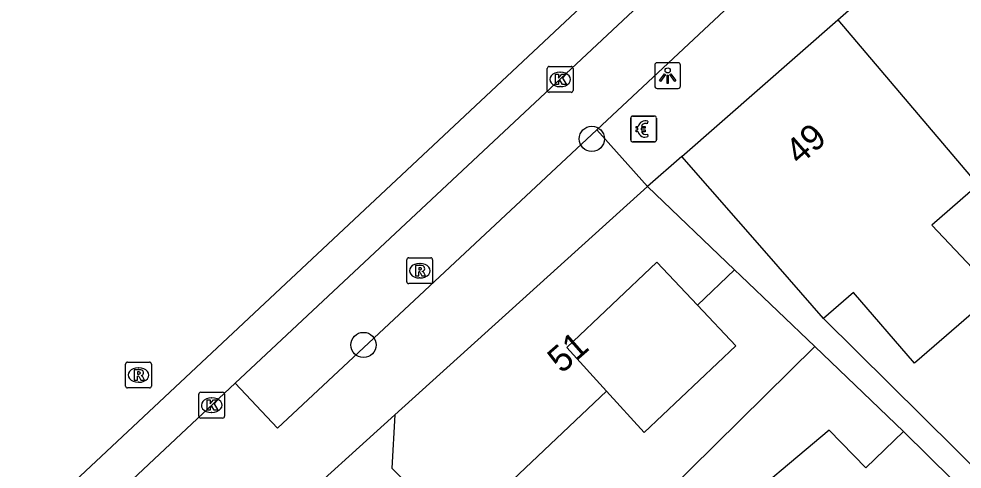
# Model space of a CAD drawing. Extents: x 160107 to 160928, y 382056 to 382918.
# Drawn here: x 160691.3 to 160727.88, y 382812.64 to 382830.08 of the extents above; entities that cross this region are included whole.
import ezdxf

# ---------------------------------------------------------------- set-up
doc = ezdxf.new("R2010")
doc.units = 0
for name, color, linetype in [('IMGEO_Betaalautomaat', 7, 'Continuous'), ('IMGEO_Boom', 7, 'Continuous'), ('IMGEO_Kolk', 7, 'Continuous'), ('IMGEO_Lichtpunt', 7, 'Continuous'), ('IMGEO_Pand', 7, 'Continuous'), ('IMGEO_Pand_nummerreeks', 7, 'Continuous'), ('IMGEO_Rijbaan_lokaal_gesloten', 7, 'Continuous'), ('IMGEO_Rioolput', 7, 'Continuous'), ('IMGEO_Voetpad_open', 7, 'Continuous')]:
    doc.layers.add(name, color=color, linetype=linetype)

msp = doc.modelspace()

# ---------------------------------------------------------------- linework, layer by layer
at = {"layer": 'IMGEO_Betaalautomaat'}
for p, q in [((160715.101, 382826.311), (160715.942, 382826.311)), ((160715.942, 382826.311), (160715.101, 382826.311)), ((160715.026, 382825.387), (160715.026, 382826.228)), ((160715.026, 382826.228), (160715.026, 382825.387)), ((160715.688, 382826.116), (160715.671, 382826.016)), ((160716.025, 382826.237), (160716.025, 382825.396)), ((160716.025, 382825.396), (160716.025, 382826.237)), ((160715.309, 382825.775), (160715.309, 382825.843)), ((160715.43, 382825.843), (160715.43, 382825.775)), ((160715.675, 382825.61), (160715.697, 382825.523)), ((160715.951, 382825.312), (160715.11, 382825.312)), ((160715.11, 382825.312), (160715.951, 382825.312))]:
    msp.add_line(p, q, dxfattribs=at)
for points in [[(160715.309, 382825.843), (160715.24, 382825.843), (160715.24, 382825.912), (160715.319, 382825.912)], [(160715.314, 382825.706), (160715.24, 382825.706), (160715.24, 382825.775), (160715.309, 382825.775)], [(160715.441, 382825.912), (160715.588, 382825.912), (160715.588, 382825.843), (160715.43, 382825.843)], [(160715.43, 382825.775), (160715.588, 382825.775), (160715.588, 382825.706), (160715.444, 382825.706)]]:
    msp.add_lwpolyline(points, dxfattribs=at)
for centre, radius, start, end in [((160715.104, 382826.234), 0.0779, 92.4484, 184.2845), ((160715.104, 382826.234), 0.0779, 92.4484, 184.2845), ((160715.948, 382826.234), 0.0779, 2.4484, 94.2845), ((160715.948, 382826.234), 0.0779, 2.4484, 94.2845), ((160715.602, 382825.836), 0.293, 73.014, 165.0139), ((160715.608, 382825.849), 0.179, 69.3236, 159.5683), ((160715.575, 382825.761), 0.267, 191.8096, 297.0389), ((160715.608, 382825.776), 0.179, 202.7625, 291.8693), ((160715.104, 382825.39), 0.0779, 182.4484, 274.2845), ((160715.104, 382825.39), 0.0779, 182.4484, 274.2845), ((160715.948, 382825.39), 0.0779, 272.4484, 4.2845), ((160715.948, 382825.39), 0.0779, 272.4484, 4.2845)]:
    msp.add_arc(centre, radius, start, end, dxfattribs=at)
at = {"layer": 'IMGEO_Boom'}
for centre in [(160713.52, 382825.428), (160704.663, 382817.445)]:
    msp.add_circle(centre, 0.489, dxfattribs=at)
at = {"layer": 'IMGEO_Kolk'}
for p, q in [((160711.788, 382827.306), (160711.788, 382828.158)), ((160711.863, 382828.232), (160712.715, 382828.232)), ((160712.789, 382828.158), (160712.789, 382827.306)), ((160712.276, 382828.012), (160712.301, 382828.012)), ((160712.299, 382827.452), (160712.274, 382827.452)), ((160712.715, 382827.232), (160711.863, 382827.232)), ((160698.276, 382814.687), (160698.276, 382815.539)), ((160698.351, 382815.613), (160699.203, 382815.613)), ((160698.764, 382815.393), (160698.789, 382815.393)), ((160699.277, 382815.539), (160699.277, 382814.687)), ((160699.203, 382814.613), (160698.351, 382814.613)), ((160698.787, 382814.833), (160698.762, 382814.833))]:
    msp.add_line(p, q, dxfattribs=at)
for points in [[(160711.788, 382827.306), (160711.788, 382828.158)], [(160711.863, 382828.232), (160712.715, 382828.232)], [(160712.789, 382828.158), (160712.789, 382827.306)], [(160712.109, 382827.932), (160712.232, 382827.932), (160712.232, 382827.781), (160712.362, 382827.932), (160712.526, 382827.932), (160712.38, 382827.781), (160712.533, 382827.532), (160712.381, 382827.532), (160712.296, 382827.696), (160712.232, 382827.629), (160712.232, 382827.532), (160712.109, 382827.532), (160712.109, 382827.932)], [(160712.715, 382827.232), (160711.863, 382827.232)], [(160698.276, 382814.687), (160698.276, 382815.539)], [(160698.351, 382815.613), (160699.203, 382815.613)], [(160699.277, 382815.539), (160699.277, 382814.687)], [(160698.597, 382815.313), (160698.72, 382815.313), (160698.72, 382815.162), (160698.85, 382815.313), (160699.014, 382815.313), (160698.868, 382815.162), (160699.021, 382814.913), (160698.869, 382814.913), (160698.784, 382815.077), (160698.72, 382815.01), (160698.72, 382814.913), (160698.597, 382814.913), (160698.597, 382815.313)], [(160699.203, 382814.613), (160698.351, 382814.613)]]:
    msp.add_lwpolyline(points, dxfattribs=at)
for centre, start, end in [((160711.865, 382828.156), 91.552, 178.448), ((160711.865, 382828.156), 91.552, 178.448), ((160712.713, 382828.156), 1.552, 88.448), ((160712.713, 382828.156), 1.552, 88.448), ((160711.865, 382827.308), 181.552, 268.448), ((160711.865, 382827.308), 181.552, 268.448), ((160712.713, 382827.308), 271.552, 358.448), ((160712.713, 382827.308), 271.552, 358.448), ((160698.353, 382815.537), 91.552, 178.448), ((160698.353, 382815.537), 91.552, 178.448), ((160699.201, 382815.537), 1.552, 88.448), ((160699.201, 382815.537), 1.552, 88.448), ((160698.353, 382814.689), 181.552, 268.448), ((160698.353, 382814.689), 181.552, 268.448), ((160699.201, 382814.689), 271.552, 358.448), ((160699.201, 382814.689), 271.552, 358.448)]:
    msp.add_arc(centre, 0.0765, start, end, dxfattribs=at)
for centre, major_axis, ratio, start_param, end_param in [((160712.275, 382827.732), (-0.387, 0.002), 0.722429, 4.712389, 7.853982), ((160712.3, 382827.732), (-0.39, 0.002), 0.717154, 1.570796, 4.712389), ((160698.763, 382815.113), (-0.387, 0.002), 0.722429, 4.712389, 7.853982), ((160698.788, 382815.113), (-0.39, 0.002), 0.717154, 1.570796, 4.712389)]:
    msp.add_ellipse(centre, major_axis=major_axis, ratio=ratio, start_param=start_param, end_param=end_param, dxfattribs=at)
at = {"layer": 'IMGEO_Lichtpunt'}
for p, q in [((160715.961, 382828.283), (160715.961, 382827.476)), ((160715.961, 382828.283), (160715.961, 382827.476)), ((160716.863, 382828.378), (160716.055, 382828.378)), ((160716.863, 382828.378), (160716.055, 382828.378)), ((160716.957, 382827.476), (160716.957, 382828.283)), ((160716.957, 382827.476), (160716.957, 382828.283)), ((160716.055, 382827.382), (160716.863, 382827.382)), ((160716.055, 382827.382), (160716.863, 382827.382))]:
    msp.add_line(p, q, dxfattribs=at)
for points in [[(160716.335, 382827.947), (160716.374, 382827.919), (160716.186, 382827.657), (160716.148, 382827.684), (160716.335, 382827.947)], [(160716.437, 382827.899), (160716.484, 382827.899), (160716.484, 382827.577), (160716.437, 382827.577), (160716.437, 382827.899)], [(160716.547, 382827.919), (160716.585, 382827.946), (160716.772, 382827.684), (160716.733, 382827.656), (160716.547, 382827.919)]]:
    msp.add_lwpolyline(points, dxfattribs=at)
msp.add_circle((160716.46, 382828.081), 0.0994, dxfattribs=at)
for centre, start, end in [((160716.055, 382828.283), 90, 180), ((160716.055, 382828.283), 90, 180), ((160716.863, 382828.283), 0, 90), ((160716.863, 382828.283), 0, 90), ((160716.055, 382827.476), 180, 270), ((160716.055, 382827.476), 180, 270), ((160716.863, 382827.476), 270, 0), ((160716.863, 382827.476), 270, 360)]:
    msp.add_arc(centre, 0.0946, start, end, dxfattribs=at)
at = {"layer": 'IMGEO_Pand'}
for points in [[(160723.059, 382830.039), (160730.515, 382836.564), (160731.934, 382836.459), (160732.286, 382836.117)], [(160717.009, 382824.744), (160723.059, 382830.039)], [(160723.059, 382830.039), (160728.206, 382823.984)], [(160722.503, 382818.469), (160720.302, 382820.982), (160717.009, 382824.744)], [(160728.206, 382823.984), (160728.499, 382823.645), (160726.7, 382822.092), (160729.183, 382819.458), (160726.032, 382816.738), (160723.669, 382819.475), (160722.503, 382818.469)], [(160715.677, 382823.578), (160705.883, 382814.742)], [(160719.055, 382820.35), (160715.677, 382823.578)], [(160717.618, 382818.991), (160716.045, 382820.653), (160712.552, 382817.349), (160714.091, 382815.655)], [(160717.618, 382818.991), (160719.055, 382820.35)], [(160722.162, 382817.382), (160719.292, 382820.124), (160719.055, 382820.35)], [(160714.091, 382815.655), (160715.548, 382814.052), (160719.106, 382817.417), (160717.618, 382818.991)], [(160711.526, 382806.902), (160722.162, 382817.382)], [(160722.162, 382817.382), (160725.599, 382814.097)], [(160708.275, 382810.155), (160714.091, 382815.655)], [(160705.883, 382814.742), (160705.764, 382812.666), (160708.275, 382810.155)], [(160725.599, 382814.097), (160724.143, 382812.683), (160722.729, 382814.139), (160718.752, 382810.812), (160720.52, 382809.009), (160718.858, 382807.347), (160722.047, 382804.158), (160720.831, 382802.942), (160719.94, 382802.051), (160718.431, 382800.542)]]:
    msp.add_lwpolyline(points, dxfattribs=at)
at = {"layer": 'IMGEO_Rijbaan_lokaal_gesloten'}
for points in [[(160684.43, 382802.132), (160687.375, 382806.113), (160689.578, 382808.541), (160717.178, 382834.369), (160719.422, 382836.368), (160722.048, 382838.543), (160729.157, 382844.12), (160732.312, 382846.426), (160736.923, 382849.508), (160740.763, 382851.737), (160802.315, 382883.934), (160804.222, 382884.588), (160817.03, 382887.143), (160818.211, 382887.624)], [(160699.691, 382815.96), (160718.332, 382833.395), (160719.619, 382834.551)], [(160694.026, 382810.658), (160699.691, 382815.96)]]:
    msp.add_lwpolyline(points, dxfattribs=at)
at = {"layer": 'IMGEO_Rioolput'}
for p, q in [((160706.418, 382820.82), (160707.27, 382820.82)), ((160706.343, 382819.894), (160706.343, 382820.746)), ((160706.831, 382820.6), (160706.856, 382820.6)), ((160707.344, 382820.746), (160707.344, 382819.894)), ((160707.27, 382819.82), (160706.418, 382819.82)), ((160706.854, 382820.04), (160706.829, 382820.04)), ((160695.44, 382815.854), (160695.44, 382816.706)), ((160695.515, 382816.78), (160696.367, 382816.78)), ((160695.928, 382816.56), (160695.953, 382816.56)), ((160696.441, 382816.706), (160696.441, 382815.854)), ((160696.367, 382815.78), (160695.515, 382815.78)), ((160695.951, 382816), (160695.926, 382816))]:
    msp.add_line(p, q, dxfattribs=at)
for points in [[(160706.418, 382820.82), (160707.27, 382820.82)], [(160706.343, 382819.894), (160706.343, 382820.746)], [(160706.932, 382820.518), (160706.68, 382820.52), (160706.68, 382820.12)], [(160707.344, 382820.746), (160707.344, 382819.894)], [(160706.68, 382820.12), (160706.804, 382820.12), (160706.804, 382820.282), (160706.815, 382820.282)], [(160706.858, 382820.439), (160706.804, 382820.439), (160706.804, 382820.358)], [(160706.804, 382820.358), (160706.856, 382820.358)], [(160706.862, 382820.253), (160706.933, 382820.12), (160707.073, 382820.12), (160707.008, 382820.246)], [(160707.27, 382819.82), (160706.418, 382819.82)], [(160695.44, 382815.854), (160695.44, 382816.706)], [(160695.515, 382816.78), (160696.367, 382816.78)], [(160696.029, 382816.478), (160695.777, 382816.48), (160695.777, 382816.08)], [(160696.441, 382816.706), (160696.441, 382815.854)], [(160695.777, 382816.08), (160695.901, 382816.08), (160695.901, 382816.242), (160695.912, 382816.242)], [(160695.955, 382816.399), (160695.901, 382816.399), (160695.901, 382816.318)], [(160695.901, 382816.318), (160695.953, 382816.318)], [(160695.959, 382816.213), (160696.03, 382816.08), (160696.17, 382816.08), (160696.105, 382816.206)], [(160696.367, 382815.78), (160695.515, 382815.78)]]:
    msp.add_lwpolyline(points, dxfattribs=at)
for centre, radius, start, end in [((160706.42, 382820.744), 0.0765, 91.552, 178.448), ((160706.42, 382820.744), 0.0765, 91.552, 178.448), ((160707.268, 382820.744), 0.0765, 1.552, 88.448), ((160707.268, 382820.744), 0.0765, 1.552, 88.448), ((160706.931, 382820.408), 0.109, 350.3612, 89.416), ((160706.814, 382820.229), 0.0533, 26.0293, 88.6989), ((160706.84, 382820.547), 0.19, 274.7715, 282.9687), ((160706.864, 382820.343), 0.0964, 77.0061, 93.1865), ((160706.878, 382820.4), 0.0378, 276.6634, 79.6772), ((160706.929, 382820.408), 0.112, 277.5842, 350.9817), ((160706.913, 382820.193), 0.108, 29.5134, 73.7905), ((160706.42, 382819.896), 0.0765, 181.552, 268.448), ((160706.42, 382819.896), 0.0765, 181.552, 268.448), ((160707.268, 382819.896), 0.0765, 271.552, 358.448), ((160707.268, 382819.896), 0.0765, 271.552, 358.448), ((160695.517, 382816.704), 0.0765, 91.552, 178.448), ((160695.517, 382816.704), 0.0765, 91.552, 178.448), ((160696.028, 382816.368), 0.109, 350.3612, 89.416), ((160696.365, 382816.704), 0.0765, 1.552, 88.448), ((160696.365, 382816.704), 0.0765, 1.552, 88.448), ((160695.911, 382816.189), 0.0533, 26.0293, 88.6989), ((160695.937, 382816.507), 0.19, 274.7715, 282.9687), ((160695.961, 382816.303), 0.0964, 77.0061, 93.1865), ((160695.975, 382816.36), 0.0378, 276.6634, 79.6772), ((160696.026, 382816.368), 0.112, 277.5842, 350.9817), ((160696.01, 382816.153), 0.108, 29.5134, 73.7905), ((160695.517, 382815.856), 0.0765, 181.552, 268.448), ((160695.517, 382815.856), 0.0765, 181.552, 268.448), ((160696.365, 382815.856), 0.0765, 271.552, 358.448), ((160696.365, 382815.856), 0.0765, 271.552, 358.448)]:
    msp.add_arc(centre, radius, start, end, dxfattribs=at)
for centre, major_axis, ratio, start_param, end_param in [((160706.83, 382820.32), (-0.387, 0.002), 0.722429, 4.712389, 7.853982), ((160706.855, 382820.32), (-0.39, 0.002), 0.717154, 1.570796, 4.712389), ((160695.927, 382816.28), (-0.387, 0.002), 0.722429, 4.712389, 7.853982), ((160695.952, 382816.28), (-0.39, 0.002), 0.717154, 1.570796, 4.712389)]:
    msp.add_ellipse(centre, major_axis=major_axis, ratio=ratio, start_param=start_param, end_param=end_param, dxfattribs=at)
at = {"layer": 'IMGEO_Voetpad_open'}
for points in [[(160721.206, 382832.736), (160720.441, 382832.064), (160713.713, 382825.78)], [(160699.691, 382815.96), (160701.334, 382814.217), (160713.713, 382825.78)], [(160713.713, 382825.78), (160715.677, 382823.578)], [(160717.009, 382824.744), (160715.677, 382823.578)], [(160722.503, 382818.469), (160730.189, 382810.858)], [(160705.883, 382814.742), (160701.633, 382810.889)], [(160725.599, 382814.097), (160736.958, 382802.907)]]:
    msp.add_lwpolyline(points, dxfattribs=at)

# ---------------------------------------------------------------- texts
at = {"layer": 'IMGEO_Pand_nummerreeks'}
for s, rotation, p in [('49', 41.1926, (160721.572, 382824.379)), ('51', 41.1899, (160712.352, 382816.31))]:
    msp.add_text(s, height=1, rotation=rotation, dxfattribs=at).set_placement(p)

doc.saveas('drawing.dxf')
